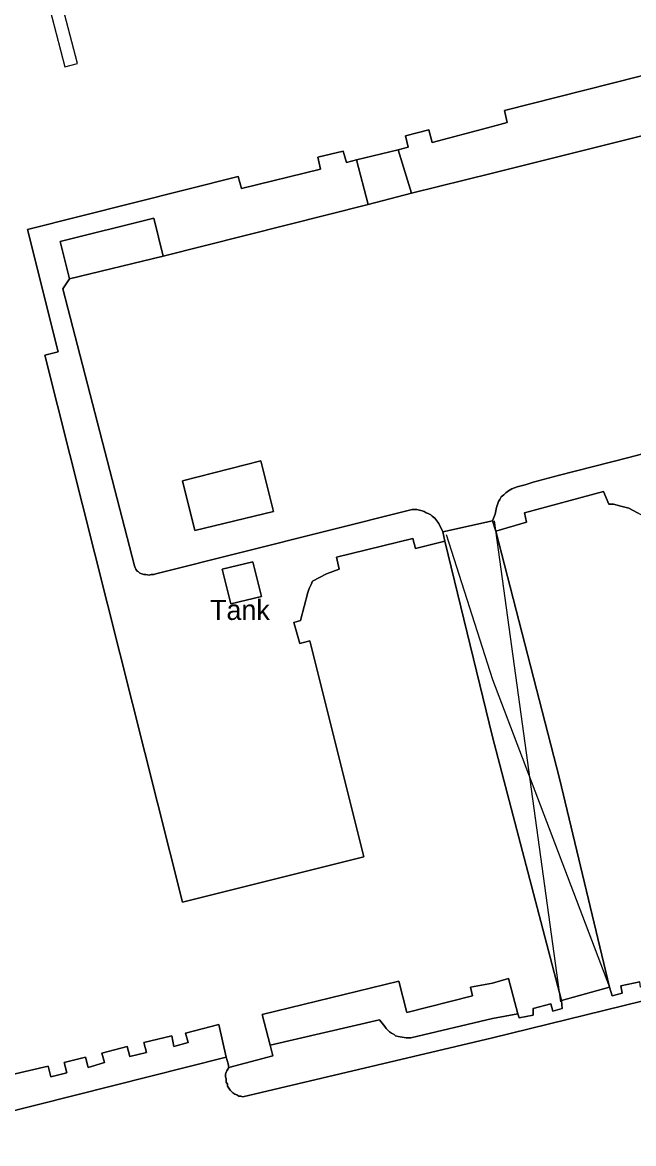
# Model space of a CAD drawing. Extents: x 529240 to 530363, y 179600 to 180767.
# Drawn here: x 529964.9 to 530010.5, y 180149.8 to 180233.6 of the extents above; entities that cross this region are included whole.
import ezdxf

# ---------------------------------------------------------------- set-up
doc = ezdxf.new("R2010")
doc.units = 0
for name, color, linetype in [('Building', 7, 'Continuous'), ('General surface', 7, 'Continuous'), ('Unclassified', 7, 'Continuous')]:
    doc.layers.add(name, color=color, linetype=linetype)

msp = doc.modelspace()

# ---------------------------------------------------------------- linework, layer by layer
at = {"layer": 'Building'}
for points in [[(529967.05, 180237.95), (529966.1, 180237.75), (529968.05, 180230.25), (529969, 180230.5)], [(529975.4, 180216.1), (529974.7, 180218.95), (529967.7, 180217.2), (529968.4, 180214.4)], [(529983.65, 180197), (529982.7, 180200.8), (529976.85, 180199.3), (529977.75, 180195.6)], [(529996.3, 180195.5), (529996.45, 180194.8), (530000, 180180.15), (530005.15, 180160.45), (530008.75, 180161.45), (530005, 180177.05), (530000.25, 180195.55), (530000, 180196.3)], [(529982.75, 180190.65), (529982.1, 180193.25), (529979.8, 180192.7), (529980.45, 180190.1)]]:
    msp.add_lwpolyline(points, close=True, dxfattribs=at)
for points in [[(529967.05, 180237.95), (529966.1, 180237.75), (529968.05, 180230.25), (529969, 180230.5), (529967.05, 180237.95)], [(529964, 180154.9), (529966.8, 180155.55), (529967, 180154.75), (529968.2, 180155.05), (529968, 180155.8), (529969.6, 180156.2), (529969.8, 180155.45), (529971, 180155.8), (529970.8, 180156.5), (529972.7, 180157), (529972.9, 180156.25), (529974.15, 180156.55), (529973.95, 180157.3), (529976.05, 180157.8), (529976.2, 180157), (529977.25, 180157.3), (529977.05, 180158), (529979.55, 180158.65), (529980.1, 180156.2), (529980.25, 180155.7), (529980.3, 180155.45), (529983.6, 180156.3), (529983.4, 180157.1), (529982.8, 180159.4), (529993, 180161.9), (529993.6, 180159.55), (529998.5, 180160.8), (529998.35, 180161.45), (530000, 180161.75), (530001.2, 180162.1), (530001.9, 180159.45), (530002, 180159.15), (530003.05, 180159.35), (530003.05, 180159.85), (530004.35, 180160.2), (530004.5, 180159.65), (530005.2, 180159.85), (530005.15, 180160.45), (530000, 180180.15), (529996.45, 180194.8), (529994.25, 180194.25), (529994.05, 180195), (529988.35, 180193.6), (529988.55, 180192.7), (529987.6, 180192.35), (529986.55, 180191.8), (529986.45, 180191.55), (529986.3, 180191.25), (529986.2, 180190.95), (529985.65, 180188.85), (529985.15, 180188.7), (529985.6, 180187.15), (529986.35, 180187.35), (529990.4, 180171.2), (529976.85, 180167.8), (529966.55, 180208.7), (529967.55, 180208.95), (529965.25, 180218.1), (529981, 180222.05), (529981.25, 180221.15), (529987.15, 180222.6), (529986.95, 180223.5), (529988.85, 180223.95), (529989.1, 180223.1), (529989.85, 180223.3), (529992.95, 180224.05), (529993.7, 180224.25), (529993.5, 180225.1), (529995.25, 180225.55), (529995.5, 180224.6), (530000, 180225.8), (530001.1, 180226.1), (530000.9, 180227), (530016.95, 180231.05)], [(530023.1, 180211.9), (530020.45, 180222.25), (530019.3, 180222), (530016.95, 180231.05), (530000.9, 180227), (530001.1, 180226.1), (530000, 180225.8), (529995.5, 180224.6), (529995.25, 180225.55), (529993.5, 180225.1), (529993.7, 180224.25), (529992.95, 180224.05)], [(529989.85, 180223.3), (529989.1, 180223.1), (529988.85, 180223.95), (529986.95, 180223.5), (529987.15, 180222.6), (529981.25, 180221.15), (529981, 180222.05), (529965.25, 180218.1), (529967.55, 180208.95), (529966.55, 180208.7), (529976.85, 180167.8), (529990.4, 180171.2), (529986.35, 180187.35), (529985.6, 180187.15), (529985.15, 180188.7), (529985.65, 180188.85), (529986.2, 180190.95), (529986.3, 180191.25), (529986.45, 180191.55), (529986.55, 180191.8), (529987.6, 180192.35), (529988.55, 180192.7), (529988.35, 180193.6), (529994.05, 180195), (529994.25, 180194.25), (529996.45, 180194.8)], [(529992.95, 180224.05), (529989.85, 180223.3)], [(530010.85, 180196.9), (530010.2, 180197.25), (530009.6, 180197.4), (530009.05, 180197.55), (530008.7, 180197.55), (530008.3, 180198.5), (530002.4, 180196.9), (530002.55, 180196.2), (530000.25, 180195.55), (530005, 180177.05), (530008.75, 180161.45), (530008.95, 180160.8), (530009.7, 180161), (530009.6, 180161.55), (530011, 180161.85)], [(530030.05, 180184.3), (530030.85, 180181.05), (530016.95, 180177.6), (530012.8, 180193.85), (530013.75, 180194.1), (530013.4, 180195.5), (530012.5, 180195.35), (530012.25, 180195.65), (530011.9, 180196.15), (530011.45, 180196.55), (530010.85, 180196.9), (530010.2, 180197.25), (530009.6, 180197.4), (530009.05, 180197.55), (530008.7, 180197.55), (530008.3, 180198.5), (530002.4, 180196.9), (530002.55, 180196.2), (530000.25, 180195.55)], [(529996.3, 180195.5), (530000, 180196.3)], [(530000.25, 180195.55), (530000, 180196.3)], [(529996.45, 180194.8), (529996.3, 180195.5)], [(530008.75, 180161.45), (530005, 180177.05), (530000.25, 180195.55)], [(529996.45, 180194.8), (530000, 180180.15), (530005.15, 180160.45)], [(529983.4, 180157.1), (529982.8, 180159.4), (529993, 180161.9), (529993.6, 180159.55), (529998.5, 180160.8), (529998.35, 180161.45), (530000, 180161.75), (530001.2, 180162.1), (530001.9, 180159.45)], [(530012.1, 180162.15), (530012.2, 180161.65), (530011.05, 180161.45), (530011, 180161.85), (530009.6, 180161.55), (530009.7, 180161), (530008.95, 180160.8), (530008.75, 180161.45)], [(530008.75, 180161.45), (530005.15, 180160.45)], [(530005.15, 180160.45), (530005.2, 180159.85), (530004.5, 180159.65), (530004.35, 180160.2), (530003.05, 180159.85), (530003.05, 180159.35), (530002, 180159.15), (530001.9, 180159.45)], [(529964, 180154.9), (529966.8, 180155.55), (529967, 180154.75), (529968.2, 180155.05), (529968, 180155.8), (529969.6, 180156.2), (529969.8, 180155.45), (529971, 180155.8), (529970.8, 180156.5), (529972.7, 180157), (529972.9, 180156.25), (529974.15, 180156.55), (529973.95, 180157.3), (529976.05, 180157.8), (529976.2, 180157), (529977.25, 180157.3), (529977.05, 180158), (529979.55, 180158.65), (529980.1, 180156.2)], [(529980.3, 180155.45), (529983.6, 180156.3), (529983.4, 180157.1)], [(529980.1, 180156.2), (529980.25, 180155.7), (529980.3, 180155.45)]]:
    msp.add_lwpolyline(points, dxfattribs=at)
at = {"layer": 'General surface'}
for points in [[(529967.05, 180237.95), (529966.1, 180237.75), (529968.05, 180230.25), (529969, 180230.5)], [(529990.7, 180219.95), (529989.85, 180223.3), (529989.1, 180223.1), (529988.85, 180223.95), (529986.95, 180223.5), (529987.15, 180222.6), (529981.25, 180221.15), (529981, 180222.05), (529965.25, 180218.1), (529967.55, 180208.95), (529966.55, 180208.7), (529976.85, 180167.8), (529990.4, 180171.2), (529986.35, 180187.35), (529985.6, 180187.15), (529985.15, 180188.7), (529985.65, 180188.85), (529986.2, 180190.95), (529986.3, 180191.25), (529986.45, 180191.55), (529986.55, 180191.8), (529987.6, 180192.35), (529988.55, 180192.7), (529988.35, 180193.6), (529994.05, 180195), (529994.25, 180194.25), (529996.45, 180194.8), (529996.3, 180195.5), (529996, 180196.1), (529995.7, 180196.5), (529995.5, 180196.65), (529995.4, 180196.75), (529995.2, 180196.85), (529995.05, 180196.9), (529994.9, 180197), (529994.75, 180197.05), (529994.35, 180197.15), (529994, 180197.15), (529974.85, 180192.35), (529974.7, 180192.3), (529974.5, 180192.3), (529974.35, 180192.25), (529974.1, 180192.3), (529973.95, 180192.3), (529973.65, 180192.4), (529973.55, 180192.5), (529973.45, 180192.55), (529973.35, 180192.7), (529973.3, 180192.8), (529973.25, 180192.95), (529967.9, 180213.65), (529968.4, 180214.4), (529967.7, 180217.2), (529974.7, 180218.95), (529975.4, 180216.1)], [(529993.95, 180220.8), (529992.95, 180224.05), (529989.85, 180223.3), (529990.7, 180219.95)], [(529983.65, 180197), (529977.75, 180195.6), (529976.85, 180199.3), (529982.7, 180200.8)], [(529982.75, 180190.65), (529980.45, 180190.1), (529979.8, 180192.7), (529982.1, 180193.25)], [(529983.4, 180157.1), (529991.55, 180159), (529991.95, 180158.5), (529992.05, 180158.35), (529992.3, 180158.1), (529992.45, 180158), (529992.65, 180157.9), (529992.75, 180157.8), (529992.95, 180157.75), (529993.55, 180157.65), (529993.9, 180157.65), (530000, 180159.1), (530001.9, 180159.45), (530001.2, 180162.1), (530000, 180161.75), (529998.35, 180161.45), (529998.5, 180160.8), (529993.6, 180159.55), (529993, 180161.9), (529982.8, 180159.4)]]:
    msp.add_lwpolyline(points, close=True, dxfattribs=at)
for points in [[(530016.95, 180231.05), (530000.9, 180227), (530001.1, 180226.1), (530000, 180225.8), (529995.5, 180224.6), (529995.25, 180225.55), (529993.5, 180225.1), (529993.7, 180224.25), (529992.95, 180224.05), (529993.95, 180220.8), (530000, 180222.3), (530013.55, 180225.7)], [(530013.55, 180225.7), (530000, 180222.3), (529993.95, 180220.8), (529990.7, 180219.95), (529975.4, 180216.1), (529968.4, 180214.4), (529967.9, 180213.65), (529973.25, 180192.95), (529973.3, 180192.8), (529973.35, 180192.7), (529973.45, 180192.55), (529973.55, 180192.5), (529973.65, 180192.4), (529973.95, 180192.3), (529974.1, 180192.3), (529974.35, 180192.25), (529974.5, 180192.3), (529974.7, 180192.3), (529974.85, 180192.35), (529994, 180197.15), (529994.35, 180197.15), (529994.75, 180197.05), (529994.9, 180197), (529995.05, 180196.9), (529995.2, 180196.85), (529995.4, 180196.75), (529995.5, 180196.65), (529995.7, 180196.5), (529996, 180196.1), (529996.3, 180195.5), (530000, 180196.3), (530000.2, 180196.8), (530000.3, 180197.3), (530000.45, 180197.75), (530000.55, 180197.9), (530000.65, 180198.1), (530000.85, 180198.25), (530001, 180198.4), (530001.2, 180198.55), (530001.45, 180198.7), (530001.85, 180198.85), (530002.45, 180199), (530003.05, 180199.2), (530004.9, 180199.7), (530010.2, 180201.05), (530012.45, 180201.65)], [(530012.45, 180201.65), (530010.2, 180201.05), (530004.9, 180199.7), (530003.05, 180199.2), (530002.45, 180199), (530001.85, 180198.85), (530001.45, 180198.7), (530001.2, 180198.55), (530001, 180198.4), (530000.85, 180198.25), (530000.65, 180198.1), (530000.55, 180197.9), (530000.45, 180197.75), (530000.3, 180197.3), (530000.2, 180196.8), (530000, 180196.3), (530000.25, 180195.55), (530002.55, 180196.2), (530002.4, 180196.9), (530008.3, 180198.5), (530008.7, 180197.55), (530009.05, 180197.55), (530009.6, 180197.4), (530010.2, 180197.25), (530010.85, 180196.9)], [(530011, 180161.85), (530009.6, 180161.55), (530009.7, 180161), (530008.95, 180160.8), (530008.75, 180161.45), (530005.15, 180160.45), (530005.2, 180159.85), (530004.5, 180159.65), (530004.35, 180160.2), (530003.05, 180159.85), (530003.05, 180159.35), (530002, 180159.15), (530001.9, 180159.45), (530000, 180159.1), (529993.9, 180157.65), (529993.55, 180157.65), (529992.95, 180157.75), (529992.75, 180157.8), (529992.65, 180157.9), (529992.45, 180158), (529992.3, 180158.1), (529992.05, 180158.35), (529991.95, 180158.5), (529991.55, 180159), (529983.4, 180157.1), (529983.6, 180156.3), (529980.3, 180155.45), (529980.15, 180155.2), (529980.1, 180155.1), (529980.05, 180154.95), (529980.05, 180154.75), (529980.1, 180154.6), (529980.1, 180154.35), (529980.2, 180154.2), (529980.2, 180154.05), (529980.4, 180153.75), (529980.6, 180153.55), (529980.75, 180153.45), (529980.9, 180153.4), (529981.05, 180153.3), (529981.2, 180153.3), (529981.35, 180153.25), (530000, 180157.65), (530011.15, 180160.4)], [(530011.15, 180160.4), (530000, 180157.65), (529981.35, 180153.25), (529981.2, 180153.3), (529981.05, 180153.3), (529980.9, 180153.4), (529980.75, 180153.45), (529980.6, 180153.55), (529980.4, 180153.75), (529980.2, 180154.05), (529980.2, 180154.2), (529980.1, 180154.35), (529980.1, 180154.6), (529980.05, 180154.75), (529980.05, 180154.95), (529980.1, 180155.1), (529980.15, 180155.2), (529980.3, 180155.45), (529980.25, 180155.7), (529980.1, 180156.2), (529954.5, 180149.75)], [(529954.5, 180149.75), (529980.1, 180156.2), (529979.55, 180158.65), (529977.05, 180158), (529977.25, 180157.3), (529976.2, 180157), (529976.05, 180157.8), (529973.95, 180157.3), (529974.15, 180156.55), (529972.9, 180156.25), (529972.7, 180157), (529970.8, 180156.5), (529971, 180155.8), (529969.8, 180155.45), (529969.6, 180156.2), (529968, 180155.8), (529968.2, 180155.05), (529967, 180154.75), (529966.8, 180155.55), (529964, 180154.9)]]:
    msp.add_lwpolyline(points, dxfattribs=at)
at = {"layer": 'Unclassified'}
for points in [[(530020.7, 180211.25), (530017.65, 180223.15), (530017.2, 180224.7), (530017.15, 180224.85), (530017, 180225.25), (530016.75, 180225.6), (530016.65, 180225.7), (530016.25, 180225.9), (530015.85, 180226), (530015.75, 180226.05), (530015.3, 180226.05), (530014.75, 180225.95), (530014.25, 180225.85), (530013.55, 180225.7), (530000, 180222.3), (529993.95, 180220.8)], [(529992.95, 180224.05), (529993.95, 180220.8)], [(529989.85, 180223.3), (529990.7, 180219.95)], [(529993.95, 180220.8), (529990.7, 180219.95)], [(529990.7, 180219.95), (529975.4, 180216.1)], [(529968.4, 180214.4), (529967.7, 180217.2), (529974.7, 180218.95), (529975.4, 180216.1)], [(529975.4, 180216.1), (529968.4, 180214.4)], [(529968.4, 180214.4), (529967.9, 180213.65), (529973.25, 180192.95), (529973.3, 180192.8), (529973.35, 180192.7), (529973.45, 180192.55), (529973.55, 180192.5), (529973.65, 180192.4), (529973.95, 180192.3), (529974.1, 180192.3), (529974.35, 180192.25), (529974.5, 180192.3), (529974.7, 180192.3), (529974.85, 180192.35), (529994, 180197.15), (529994.35, 180197.15), (529994.75, 180197.05), (529994.9, 180197), (529995.05, 180196.9), (529995.2, 180196.85), (529995.4, 180196.75), (529995.5, 180196.65), (529995.7, 180196.5), (529996, 180196.1), (529996.3, 180195.5)], [(530012.45, 180201.65), (530010.2, 180201.05), (530004.9, 180199.7), (530003.05, 180199.2), (530002.45, 180199), (530001.85, 180198.85), (530001.45, 180198.7), (530001.2, 180198.55), (530001, 180198.4), (530000.85, 180198.25), (530000.65, 180198.1), (530000.55, 180197.9), (530000.45, 180197.75), (530000.3, 180197.3), (530000.2, 180196.8), (530000, 180196.3)], [(529983.65, 180197), (529982.7, 180200.8), (529976.85, 180199.3), (529977.75, 180195.6), (529983.65, 180197)], [(530005.1, 180160.35), (530000.15, 180196.3)], [(529996.55, 180195.3), (530000, 180184.45), (530008.75, 180161.45)], [(529982.75, 180190.65), (529980.45, 180190.1), (529979.8, 180192.7), (529982.1, 180193.25), (529982.75, 180190.65)], [(529980.3, 180155.45), (529980.15, 180155.2), (529980.1, 180155.1), (529980.05, 180154.95), (529980.05, 180154.75), (529980.1, 180154.6), (529980.1, 180154.35), (529980.2, 180154.2), (529980.2, 180154.05), (529980.4, 180153.75), (529980.6, 180153.55), (529980.75, 180153.45), (529980.9, 180153.4), (529981.05, 180153.3), (529981.2, 180153.3), (529981.35, 180153.25), (530000, 180157.65), (530011.15, 180160.4)], [(529983.4, 180157.1), (529991.55, 180159), (529991.95, 180158.5), (529992.05, 180158.35), (529992.3, 180158.1), (529992.45, 180158), (529992.65, 180157.9), (529992.75, 180157.8), (529992.95, 180157.75), (529993.55, 180157.65), (529993.9, 180157.65), (530000, 180159.1), (530001.9, 180159.45)], [(529954.5, 180149.75), (529980.1, 180156.2)]]:
    msp.add_lwpolyline(points, dxfattribs=at)

# ---------------------------------------------------------------- texts
msp.add_text('Tank', height=1.5, dxfattribs=at).set_placement((529978.9, 180188.9))

doc.saveas('drawing.dxf')
